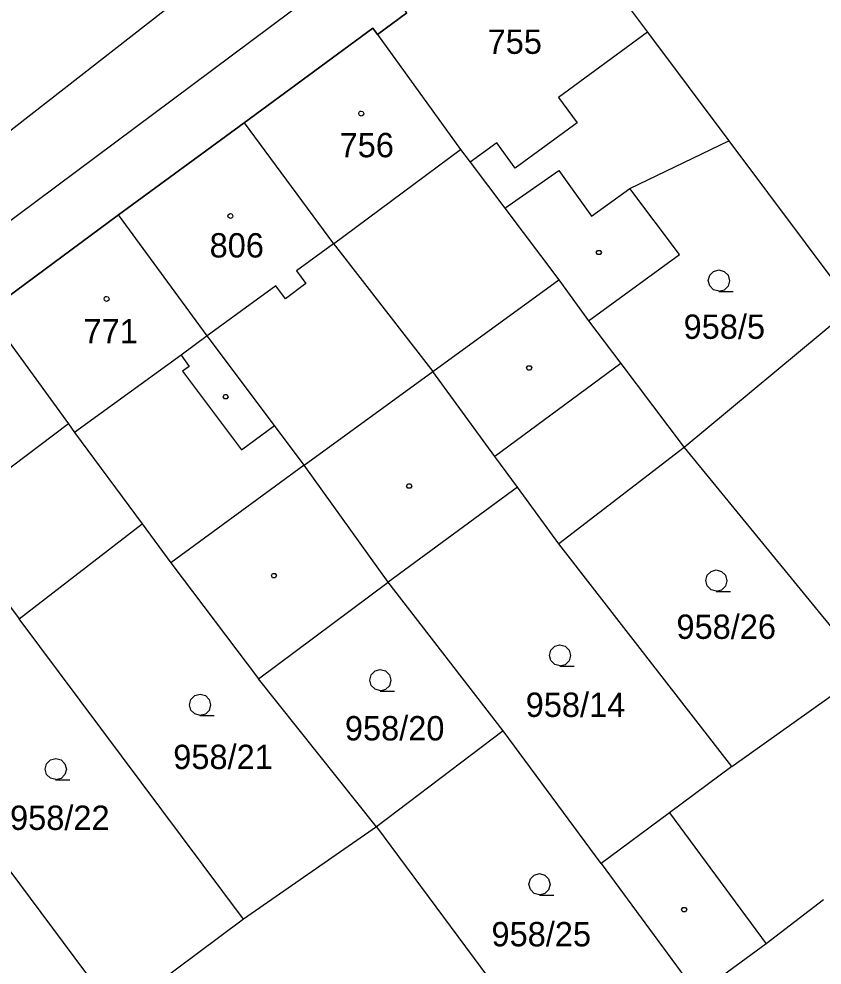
# Model space of a CAD drawing. Extents: x -777309 to -774195, y -1144706 to -1143600.
# Drawn here: x -775241.8 to -775185.7, y -1144635.7 to -1144569.6 of the extents above; entities that cross this region are included whole.
import ezdxf

# ---------------------------------------------------------------- set-up
doc = ezdxf.new("R2010")
doc.units = 0
for name, color, linetype in [('1', 7, 'Continuous'), ('11', 7, 'Continuous'), ('12', 7, 'Continuous'), ('2', 7, 'Continuous'), ('3', 7, 'Continuous'), ('4', 7, 'Continuous'), ('5', 7, 'Continuous')]:
    doc.layers.add(name, color=color, linetype=linetype)

msp = doc.modelspace()

# ---------------------------------------------------------------- linework, layer by layer
at = {"layer": '1'}
for p, q in [((-775204.58, -1144561.67), (-775197.93, -1144570.55)), ((-775214.74, -1144569.21), (-775216.8, -1144570.72)), ((-775217.13, -1144570.28), (-775226.12, -1144576.88)), ((-775216.8, -1144570.72), (-775217.13, -1144570.28)), ((-775216.8, -1144570.72), (-775211, -1144578.74)), ((-775197.93, -1144570.55), (-775192.26, -1144578.14)), ((-775226.12, -1144576.88), (-775234.89, -1144583.32)), ((-775226.12, -1144576.88), (-775219.86, -1144585.33)), ((-775199.16, -1144581.48), (-775192.26, -1144578.14)), ((-775192.26, -1144578.14), (-775183.58, -1144589.75)), ((-775211, -1144578.74), (-775210.33, -1144579.64)), ((-775210.33, -1144579.64), (-775207.91, -1144582.84)), ((-775195.7, -1144586.07), (-775199.16, -1144581.48)), ((-775234.89, -1144583.32), (-775244.08, -1144590.11)), ((-775228.69, -1144591.76), (-775234.89, -1144583.32)), ((-775207.91, -1144582.84), (-775204.14, -1144587.85)), ((-775219.86, -1144585.33), (-775219.74, -1144585.49)), ((-775219.74, -1144585.49), (-775212.93, -1144594.24)), ((-775202.06, -1144590.71), (-775195.7, -1144586.07)), ((-775204.14, -1144587.85), (-775202.06, -1144590.71)), ((-775183.58, -1144589.75), (-775195.38, -1144599.55)), ((-775244.08, -1144590.11), (-775238.38, -1144597.91)), ((-775202.06, -1144590.71), (-775199.8, -1144593.7)), ((-775224, -1144598.02), (-775228.69, -1144591.76)), ((-775199.8, -1144593.7), (-775195.38, -1144599.55)), ((-775208.59, -1144600.18), (-775212.93, -1144594.24)), ((-775238.38, -1144597.91), (-775237.95, -1144598.5)), ((-775221.92, -1144600.8), (-775224, -1144598.02)), ((-775237.95, -1144598.5), (-775233.23, -1144604.89)), ((-775195.38, -1144599.55), (-775204.14, -1144606.28)), ((-775195.38, -1144599.55), (-775182.64, -1144615.12)), ((-775207.02, -1144602.33), (-775208.59, -1144600.18)), ((-775216.06, -1144608.95), (-775221.92, -1144600.8)), ((-775207.02, -1144602.33), (-775216.06, -1144608.95)), ((-775204.14, -1144606.28), (-775207.02, -1144602.33)), ((-775241.83, -1144611.53), (-775233.23, -1144604.89)), ((-775233.23, -1144604.89), (-775231.24, -1144607.61)), ((-775192.04, -1144621.83), (-775204.14, -1144606.28)), ((-775231.24, -1144607.61), (-775225.1, -1144615.7)), ((-775243.69, -1144609.04), (-775241.83, -1144611.53)), ((-775225.1, -1144615.7), (-775216.06, -1144608.95)), ((-775208.02, -1144619.35), (-775216.06, -1144608.95)), ((-775226.16, -1144632.49), (-775241.83, -1144611.53)), ((-775192.04, -1144621.83), (-775182.64, -1144615.12)), ((-775235.02, -1144639.1), (-775252.61, -1144615.53)), ((-775216.86, -1144626.05), (-775225.1, -1144615.7)), ((-775208.02, -1144619.35), (-775216.86, -1144626.05)), ((-775201.17, -1144628.6), (-775208.02, -1144619.35)), ((-775192.04, -1144621.83), (-775196.41, -1144625.07)), ((-775196.41, -1144625.07), (-775201.17, -1144628.6)), ((-775216.86, -1144626.05), (-775226.16, -1144632.49)), ((-775216.86, -1144626.05), (-775203.97, -1144643.39)), ((-775201.17, -1144628.6), (-775195, -1144636.98)), ((-775185.64, -1144631.15), (-775189.64, -1144634.21)), ((-775226.16, -1144632.49), (-775235.02, -1144639.1)), ((-775189.64, -1144634.21), (-775194.46, -1144637.72))]:
    msp.add_line(p, q, dxfattribs=at)
at = {"layer": '11'}
msp.add_lwpolyline([(-775320.64, -1144646.86), (-775315.54, -1144643.07), (-775315.63, -1144642.95), (-775311.83, -1144640.13), (-775311.74, -1144640.25), (-775307.84, -1144637.35), (-775294.95, -1144627.78), (-775285.39, -1144620.71), (-775281.93, -1144618.14), (-775282.02, -1144618.02), (-775278.17, -1144615.17), (-775278.08, -1144615.29), (-775274.06, -1144612.3), (-775269.14, -1144608.66), (-775261.98, -1144603.34), (-775252.95, -1144596.66), (-775244.08, -1144590.11), (-775234.89, -1144583.32), (-775226.12, -1144576.88), (-775217.13, -1144570.28), (-775216.8, -1144570.72), (-775214.74, -1144569.21), (-775215.07, -1144568.77), (-775206.87, -1144562.75)], dxfattribs=at)
at = {"layer": '12'}
for p, q in [((-775204.58, -1144561.67), (-775197.93, -1144570.55)), ((-775214.74, -1144569.21), (-775216.8, -1144570.72)), ((-775217.13, -1144570.28), (-775226.12, -1144576.88)), ((-775216.8, -1144570.72), (-775217.13, -1144570.28)), ((-775216.8, -1144570.72), (-775211, -1144578.74)), ((-775216.8, -1144570.72), (-775211, -1144578.74)), ((-775197.93, -1144570.55), (-775204.16, -1144575.11)), ((-775204.16, -1144575.11), (-775202.86, -1144576.89)), ((-775226.12, -1144576.88), (-775234.89, -1144583.32)), ((-775226.12, -1144576.88), (-775219.86, -1144585.33)), ((-775226.12, -1144576.88), (-775219.86, -1144585.33)), ((-775202.86, -1144576.89), (-775207.18, -1144580.04)), ((-775219.86, -1144585.33), (-775211, -1144578.74)), ((-775211, -1144578.74), (-775210.33, -1144579.64)), ((-775208.47, -1144578.28), (-775210.33, -1144579.64)), ((-775207.18, -1144580.04), (-775208.47, -1144578.28)), ((-775234.89, -1144583.32), (-775244.08, -1144590.11)), ((-775228.69, -1144591.76), (-775234.89, -1144583.32)), ((-775228.69, -1144591.76), (-775234.89, -1144583.32)), ((-775219.86, -1144585.33), (-775222.45, -1144587.21)), ((-775222.45, -1144587.21), (-775221.8, -1144588.1)), ((-775221.8, -1144588.1), (-775223.23, -1144589.17)), ((-775223.89, -1144588.26), (-775228.69, -1144591.76)), ((-775223.23, -1144589.17), (-775223.89, -1144588.26)), ((-775244.08, -1144590.11), (-775238.38, -1144597.91)), ((-775244.08, -1144590.11), (-775238.38, -1144597.91)), ((-775228.69, -1144591.76), (-775230.52, -1144593.12)), ((-775230.52, -1144593.12), (-775237.95, -1144598.5)), ((-775238.38, -1144597.91), (-775247.1, -1144604.48)), ((-775238.38, -1144597.91), (-775237.95, -1144598.5))]:
    msp.add_line(p, q, dxfattribs=at)
at = {"layer": '3'}
for points in [[(-775192.94, -1144588.64), (-775193.32, -1144588.54), (-775193.59, -1144588.27), (-775193.69, -1144587.9), (-775193.59, -1144587.53), (-775193.32, -1144587.26), (-775192.95, -1144587.16), (-775192.58, -1144587.26), (-775192.31, -1144587.53), (-775192.21, -1144587.91), (-775192.31, -1144588.29), (-775192.58, -1144588.56), (-775192.96, -1144588.66), (-775191.96, -1144588.66)], [(-775193.12, -1144609.59), (-775193.5, -1144609.49), (-775193.77, -1144609.22), (-775193.87, -1144608.85), (-775193.77, -1144608.48), (-775193.5, -1144608.21), (-775193.13, -1144608.11), (-775192.76, -1144608.21), (-775192.49, -1144608.48), (-775192.39, -1144608.86), (-775192.49, -1144609.24), (-775192.76, -1144609.51), (-775193.14, -1144609.61), (-775192.14, -1144609.61)], [(-775204.04, -1144614.81), (-775204.42, -1144614.71), (-775204.69, -1144614.44), (-775204.79, -1144614.07), (-775204.69, -1144613.7), (-775204.42, -1144613.43), (-775204.05, -1144613.33), (-775203.68, -1144613.43), (-775203.41, -1144613.7), (-775203.31, -1144614.08), (-775203.41, -1144614.46), (-775203.68, -1144614.73), (-775204.06, -1144614.83), (-775203.06, -1144614.83)], [(-775216.59, -1144616.54), (-775216.97, -1144616.44), (-775217.24, -1144616.17), (-775217.34, -1144615.8), (-775217.24, -1144615.43), (-775216.97, -1144615.16), (-775216.6, -1144615.06), (-775216.23, -1144615.16), (-775215.96, -1144615.43), (-775215.86, -1144615.81), (-775215.96, -1144616.19), (-775216.23, -1144616.46), (-775216.61, -1144616.56), (-775215.61, -1144616.56)], [(-775229.18, -1144618.26), (-775229.56, -1144618.16), (-775229.83, -1144617.89), (-775229.93, -1144617.52), (-775229.83, -1144617.15), (-775229.56, -1144616.88), (-775229.19, -1144616.78), (-775228.82, -1144616.88), (-775228.55, -1144617.15), (-775228.45, -1144617.53), (-775228.55, -1144617.91), (-775228.82, -1144618.18), (-775229.2, -1144618.28), (-775228.2, -1144618.28)], [(-775239.26, -1144622.75), (-775239.64, -1144622.65), (-775239.91, -1144622.38), (-775240.01, -1144622.01), (-775239.91, -1144621.64), (-775239.64, -1144621.37), (-775239.27, -1144621.27), (-775238.9, -1144621.37), (-775238.63, -1144621.64), (-775238.53, -1144622.02), (-775238.63, -1144622.4), (-775238.9, -1144622.67), (-775239.28, -1144622.77), (-775238.28, -1144622.77)], [(-775205.47, -1144630.79), (-775205.85, -1144630.69), (-775206.12, -1144630.42), (-775206.22, -1144630.05), (-775206.12, -1144629.68), (-775205.85, -1144629.41), (-775205.48, -1144629.31), (-775205.11, -1144629.41), (-775204.84, -1144629.68), (-775204.74, -1144630.06), (-775204.84, -1144630.44), (-775205.11, -1144630.71), (-775205.49, -1144630.81), (-775204.49, -1144630.81)]]:
    msp.add_lwpolyline(points, dxfattribs=at)
at = {"layer": '4'}
for p, q in [((-775269.86, -1144598.82), (-775222.72, -1144562.02)), ((-775219.39, -1144566.53), (-775352.58, -1144665.72)), ((-775197.93, -1144570.55), (-775204.16, -1144575.11)), ((-775204.16, -1144575.11), (-775202.86, -1144576.89)), ((-775202.86, -1144576.89), (-775207.18, -1144580.04)), ((-775219.86, -1144585.33), (-775211, -1144578.74)), ((-775208.47, -1144578.28), (-775210.33, -1144579.64)), ((-775207.18, -1144580.04), (-775208.47, -1144578.28)), ((-775207.91, -1144582.84), (-775204.12, -1144580.22)), ((-775204.12, -1144580.22), (-775201.85, -1144583.4)), ((-775201.85, -1144583.4), (-775199.16, -1144581.48)), ((-775219.86, -1144585.33), (-775222.45, -1144587.21)), ((-775222.45, -1144587.21), (-775221.8, -1144588.1)), ((-775221.8, -1144588.1), (-775223.23, -1144589.17)), ((-775212.93, -1144594.24), (-775204.14, -1144587.85)), ((-775223.89, -1144588.26), (-775228.69, -1144591.76)), ((-775223.23, -1144589.17), (-775223.89, -1144588.26)), ((-775228.69, -1144591.76), (-775230.52, -1144593.12)), ((-775230.52, -1144593.12), (-775237.95, -1144598.5)), ((-775230.52, -1144593.12), (-775229.96, -1144593.9)), ((-775229.96, -1144593.9), (-775230.41, -1144594.23)), ((-775199.8, -1144593.7), (-775208.59, -1144600.18)), ((-775230.41, -1144594.23), (-775226.29, -1144599.73)), ((-775221.92, -1144600.8), (-775212.93, -1144594.24)), ((-775238.38, -1144597.91), (-775247.1, -1144604.48)), ((-775226.29, -1144599.73), (-775224, -1144598.02)), ((-775221.92, -1144600.8), (-775231.24, -1144607.61)), ((-775196.41, -1144625.07), (-775189.64, -1144634.21))]:
    msp.add_line(p, q, dxfattribs=at)
at = {"layer": '5'}
for points in [[(-775217.93, -1144576.07), (-775217.83, -1144576.09), (-775217.78, -1144576.18), (-775217.76, -1144576.24), (-775217.78, -1144576.33), (-775217.86, -1144576.4), (-775217.93, -1144576.41), (-775218.02, -1144576.38), (-775218.08, -1144576.32), (-775218.1, -1144576.24), (-775218.08, -1144576.15), (-775218, -1144576.08)], [(-775227.07, -1144583.22), (-775226.97, -1144583.24), (-775226.92, -1144583.33), (-775226.9, -1144583.39), (-775226.92, -1144583.48), (-775227, -1144583.55), (-775227.07, -1144583.56), (-775227.16, -1144583.53), (-775227.22, -1144583.47), (-775227.24, -1144583.39), (-775227.22, -1144583.3), (-775227.14, -1144583.23)], [(-775201.25, -1144585.79), (-775201.16, -1144585.94), (-775201.25, -1144586.09), (-775201.43, -1144586.09), (-775201.52, -1144585.94), (-775201.43, -1144585.79)], [(-775235.72, -1144589.01), (-775235.62, -1144589.03), (-775235.57, -1144589.12), (-775235.55, -1144589.18), (-775235.57, -1144589.27), (-775235.65, -1144589.34), (-775235.72, -1144589.35), (-775235.81, -1144589.32), (-775235.87, -1144589.26), (-775235.89, -1144589.18), (-775235.87, -1144589.09), (-775235.79, -1144589.02)], [(-775206.11, -1144593.85), (-775206.02, -1144594), (-775206.11, -1144594.15), (-775206.29, -1144594.15), (-775206.38, -1144594), (-775206.29, -1144593.85)], [(-775227.31, -1144595.86), (-775227.22, -1144596.01), (-775227.31, -1144596.16), (-775227.49, -1144596.16), (-775227.58, -1144596.01), (-775227.49, -1144595.86)], [(-775214.49, -1144602.1), (-775214.4, -1144602.25), (-775214.49, -1144602.4), (-775214.67, -1144602.4), (-775214.76, -1144602.25), (-775214.67, -1144602.1)], [(-775223.94, -1144608.35), (-775223.85, -1144608.5), (-775223.94, -1144608.65), (-775224.12, -1144608.65), (-775224.21, -1144608.5), (-775224.12, -1144608.35)], [(-775195.28, -1144631.67), (-775195.19, -1144631.82), (-775195.28, -1144631.97), (-775195.46, -1144631.97), (-775195.55, -1144631.82), (-775195.46, -1144631.67)]]:
    msp.add_lwpolyline(points, close=True, dxfattribs=at)

# ---------------------------------------------------------------- texts
at = {"layer": '2'}
for s, p in [('755', (-775209.103, -1144572.07)), ('756', (-775219.443, -1144579.29)), ('806', (-775228.523, -1144586.29)), ('771', (-775237.333, -1144592.29)), ('958/5', (-775195.413, -1144591.97)), ('958/26', (-775195.913, -1144612.92)), ('958/14', (-775206.443, -1144618.37)), ('958/20', (-775219.073, -1144620.01)), ('958/21', (-775231.063, -1144622.01)), ('958/22', (-775242.463, -1144626.26)), ('958/25', (-775208.833, -1144634.39))]:
    msp.add_text(s, height=1.7, dxfattribs=at).set_placement(p)

doc.saveas('drawing.dxf')
